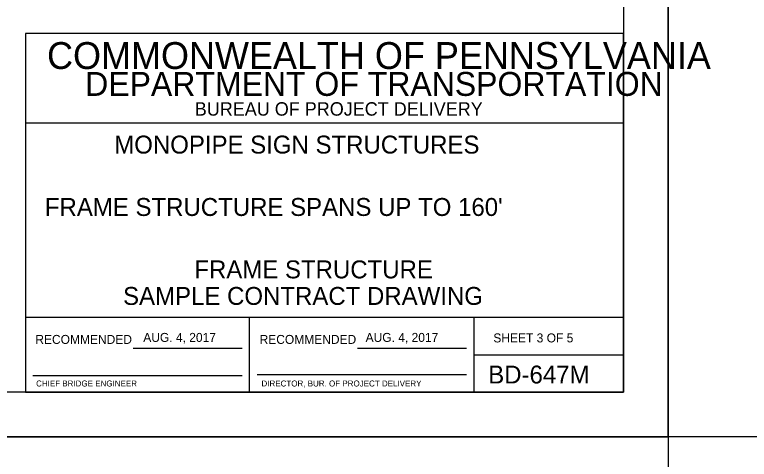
# Model space of a CAD drawing. Extents: x 640117 to 642655, y 297247 to 298435.
# Drawn here: x 641580.9 to 641826.6, y 297834 to 297982.8 of the extents above; entities that cross this region are included whole.
import ezdxf

# ---------------------------------------------------------------- set-up
doc = ezdxf.new("R2010")
doc.units = 0
for name, color, linetype in [('1', 7, 'Continuous'), ('10', 7, 'Continuous'), ('2', 7, 'Continuous'), ('52', 7, 'Continuous'), ('PLT-BNDY', 7, 'Continuous')]:
    doc.layers.add(name, color=color, linetype=linetype)

msp = doc.modelspace()

# ---------------------------------------------------------------- linework, layer by layer
at = {"layer": '1'}
for p, q in [((641659.46, 297856.46), (641659.46, 297881.46)), ((641620.54, 297871.17), (641656.96, 297871.17)), ((641695.54, 297871.17), (641731.96, 297871.17)), ((641586.96, 297861.96), (641656.96, 297861.96)), ((641661.96, 297862.33), (641731.96, 297862.33))]:
    msp.add_line(p, q, dxfattribs=at)
at = {"layer": '2'}
for p, q in [((641784.46, 298420.46), (641784.46, 297856.46)), ((641784.46, 297976.46), (641584.46, 297976.46)), ((641584.46, 297976.46), (641584.46, 297856.46)), ((641784.46, 297856.46), (641784.46, 297976.46)), ((641784.46, 297946.46), (641584.46, 297946.46)), ((641784.46, 297881.46), (641584.46, 297881.46)), ((641734.46, 297881.46), (641734.46, 297856.46)), ((641734.46, 297868.96), (641784.46, 297868.96)), ((641784.46, 297856.46), (640998.46, 297856.46)), ((641584.46, 297856.46), (641784.46, 297856.46))]:
    msp.add_line(p, q, dxfattribs=at)
at = {"layer": 'PLT-BNDY'}
for points in [[(640958.46, 298435.46), (641799.46, 298435.46), (641799.46, 297841.46), (640958.46, 297841.46)], [(641799.46, 298435.46), (642640.46, 298435.46), (642640.46, 297841.46), (641799.46, 297841.46)], [(640958.46, 297841.46), (641799.46, 297841.46), (641799.46, 297247.46), (640958.46, 297247.46)]]:
    msp.add_lwpolyline(points, close=True, dxfattribs=at)

# ---------------------------------------------------------------- texts
at = {"layer": '1'}
for s, height, p in [('RECOMMENDED', 3, (641587.79, 297872.58)), ('RECOMMENDED', 3, (641662.79, 297872.58)), ('CHIEF BRIDGE ENGINEER', 2.0002, (641588.05, 297858.33)), ('DIRECTOR, BUR. OF PROJECT DELIVERY', 2.0002, (641663.43, 297858.33))]:
    msp.add_text(s, height=height, dxfattribs=at).set_placement(p)
at = {"layer": '10'}
for s, p in [('MONOPIPE SIGN STRUCTURES', (641614.18, 297936.28)), ("FRAME STRUCTURE SPANS UP TO 160'", (641590.98, 297915.4)), ('FRAME STRUCTURE', (641640.97, 297894.51)), ('SAMPLE CONTRACT DRAWING', (641617.13, 297885.63)), ('BD-647M', (641739.25, 297859.33))]:
    msp.add_text(s, height=6, dxfattribs=at).set_placement(p)
at = {"layer": '2'}
for s, height, p in [('COMMONWEALTH OF PENNSYLVANIA', 9, (641591.71, 297964.58)), ('DEPARTMENT OF TRANSPORTATION', 8.0002, (641604.46, 297955.58)), ('BUREAU OF PROJECT DELIVERY', 4.5, (641641.12, 297948.96)), ('SHEET 3 OF 5', 3, (641740.97, 297873.08))]:
    msp.add_text(s, height=height, dxfattribs=at).set_placement(p)
at = {"layer": '52'}
for p in [(641623.89, 297873.25), (641698.25, 297873.25)]:
    msp.add_text('AUG. 4, 2017', height=3, dxfattribs=at).set_placement(p)

doc.saveas('drawing.dxf')
